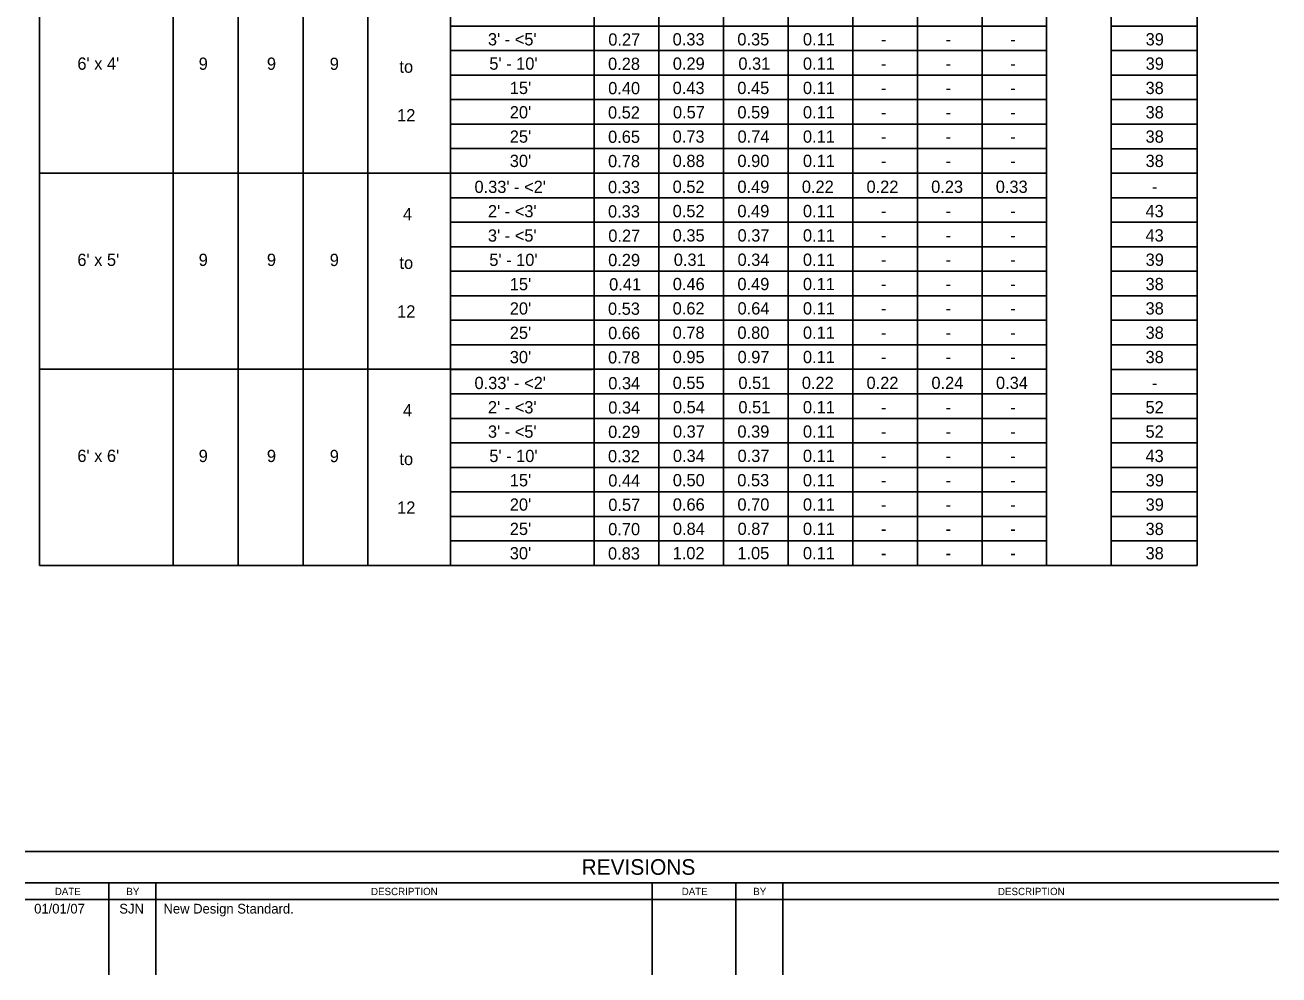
# Model space of a CAD drawing. Extents: x 10338.56 to 10340.78, y 76371.55 to 76372.62.
# Drawn here: x 10338.562 to 10339.206, y 76371.549 to 76372.037 of the extents above; entities that cross this region are included whole.
import ezdxf

# ---------------------------------------------------------------- set-up
doc = ezdxf.new("R2010")
doc.units = 0
for name, color, linetype in [('AdhocPoint_dp', 7, 'Continuous'), ('Border', 7, 'Continuous'), ('PlotBorder_dp', 7, 'Continuous')]:
    doc.layers.add(name, color=color, linetype=linetype)

msp = doc.modelspace()

# ---------------------------------------------------------------- linework, layer by layer
at = {"layer": 'Border'}
for p, q in [((10339.20638, 76371.61194), (10338.56226, 76371.61194)), ((10339.20638, 76371.59585), (10338.56226, 76371.59585)), ((10338.60528, 76371.59585), (10338.60528, 76371.54851)), ((10338.62945, 76371.59585), (10338.62945, 76371.54851)), ((10338.88433, 76371.59585), (10338.88433, 76371.54851)), ((10338.92735, 76371.59585), (10338.92735, 76371.54851)), ((10338.95152, 76371.59585), (10338.95152, 76371.54851)), ((10338.56226, 76371.58731), (10339.20638, 76371.58731))]:
    msp.add_line(p, q, dxfattribs=at)
at = {"layer": 'PlotBorder_dp'}
for p, q in [((10338.5697, 76372.53475), (10338.5697, 76371.75893)), ((10339.16444, 76372.53475), (10339.16444, 76371.75893)), ((10338.63833, 76372.51488), (10338.63833, 76371.75893)), ((10338.78078, 76372.51488), (10338.78078, 76371.75893)), ((10338.85466, 76372.51488), (10338.85466, 76371.75893)), ((10339.12025, 76372.51488), (10339.12025, 76371.75893)), ((10338.67169, 76372.50228), (10338.67169, 76371.75893)), ((10338.70506, 76372.50228), (10338.70506, 76371.75893)), ((10338.73842, 76372.50228), (10338.73842, 76371.75893)), ((10338.88786, 76372.47713), (10338.88786, 76371.75893)), ((10338.92106, 76372.47713), (10338.92106, 76371.75893)), ((10338.95425, 76372.47713), (10338.95425, 76371.75893)), ((10338.98745, 76372.47713), (10338.98745, 76371.75893)), ((10339.02065, 76372.47713), (10339.02065, 76371.75893)), ((10339.02065, 76372.47713), (10339.02065, 76371.75893)), ((10339.05385, 76372.47713), (10339.05385, 76371.75893)), ((10339.08705, 76372.47713), (10339.08705, 76371.75893)), ((10338.78078, 76372.03613), (10339.08705, 76372.03613)), ((10339.12025, 76372.03611), (10339.16444, 76372.03611)), ((10338.78078, 76372.02353), (10339.08705, 76372.02353)), ((10339.12025, 76372.02351), (10339.16444, 76372.02351)), ((10338.78078, 76372.01093), (10339.08705, 76372.01093)), ((10339.12025, 76372.01091), (10339.16444, 76372.01091)), ((10338.78078, 76371.99833), (10339.08705, 76371.99833)), ((10339.12025, 76371.99831), (10339.16444, 76371.99831)), ((10338.78078, 76371.98573), (10339.08705, 76371.98573)), ((10339.12025, 76371.98571), (10339.16444, 76371.98571)), ((10338.78078, 76371.97313), (10339.08705, 76371.97313)), ((10339.12025, 76371.97311), (10339.16444, 76371.97311)), ((10338.5697, 76371.96053), (10339.08705, 76371.96053)), ((10338.78139, 76371.96051), (10338.85356, 76371.96051)), ((10338.78139, 76371.96051), (10338.85356, 76371.96051)), ((10339.12025, 76371.96051), (10339.16444, 76371.96051)), ((10338.78078, 76371.94793), (10339.08705, 76371.94793)), ((10339.12025, 76371.94791), (10339.16444, 76371.94791)), ((10338.78078, 76371.93533), (10339.08705, 76371.93533)), ((10339.12025, 76371.93531), (10339.16444, 76371.93531)), ((10338.78078, 76371.92273), (10339.08705, 76371.92273)), ((10339.12025, 76371.92271), (10339.16444, 76371.92271)), ((10338.78078, 76371.91013), (10339.08705, 76371.91013)), ((10339.12025, 76371.91011), (10339.16444, 76371.91011)), ((10338.78078, 76371.89753), (10339.08705, 76371.89753)), ((10339.12025, 76371.89751), (10339.16444, 76371.89751)), ((10338.78078, 76371.88493), (10339.08705, 76371.88493)), ((10339.12025, 76371.88491), (10339.16444, 76371.88491)), ((10338.78078, 76371.87233), (10339.08705, 76371.87233)), ((10339.12025, 76371.87231), (10339.16444, 76371.87231)), ((10338.5697, 76371.85973), (10339.08705, 76371.85973)), ((10338.78139, 76371.85971), (10338.85356, 76371.85971)), ((10338.78139, 76371.85971), (10338.85356, 76371.85971)), ((10338.78139, 76371.85971), (10338.85356, 76371.85971)), ((10339.12025, 76371.85971), (10339.16444, 76371.85971)), ((10338.78078, 76371.84713), (10339.08705, 76371.84713)), ((10339.12025, 76371.84711), (10339.16444, 76371.84711)), ((10338.78078, 76371.83453), (10339.08705, 76371.83453)), ((10339.12025, 76371.83451), (10339.16444, 76371.83451)), ((10338.78078, 76371.82193), (10339.08705, 76371.82193)), ((10339.12025, 76371.82191), (10339.16444, 76371.82191)), ((10338.78078, 76371.80933), (10339.08705, 76371.80933)), ((10339.12025, 76371.80931), (10339.16444, 76371.80931)), ((10338.78078, 76371.79673), (10339.08705, 76371.79673)), ((10339.12025, 76371.79671), (10339.16444, 76371.79671)), ((10338.78078, 76371.78413), (10339.08705, 76371.78413)), ((10339.12025, 76371.78411), (10339.16444, 76371.78411)), ((10338.78078, 76371.77153), (10339.08705, 76371.77153)), ((10339.12025, 76371.77151), (10339.16444, 76371.77151)), ((10338.5697, 76371.75893), (10339.16444, 76371.75893)), ((10338.78139, 76371.75891), (10338.85356, 76371.75891))]:
    msp.add_line(p, q, dxfattribs=at)

# ---------------------------------------------------------------- texts
at = {"layer": 'AdhocPoint_dp'}
for s, height, p in [('9', 0.0063, (10338.65145, 76372.01363)), ('9', 0.0063, (10338.68649, 76372.01363)), ('9', 0.0063, (10338.71878, 76372.01357)), ('9', 0.0063, (10338.65145, 76371.91285)), ('9', 0.0063, (10338.68649, 76371.91285)), ('9', 0.0063, (10338.71878, 76371.91279)), ('9', 0.0063, (10338.65145, 76371.81206)), ('9', 0.0063, (10338.68649, 76371.81206)), ('9', 0.0063, (10338.71878, 76371.81201)), ('REVISIONS', 0.008022, (10338.84816, 76371.59996)), ('BY', 0.003753, (10338.61427, 76371.58952)), ('BY', 0.003753, (10338.93633, 76371.58952)), ('01/01/07', 0.005, (10338.56694, 76371.58005)), ('SJN', 0.005, (10338.61067, 76371.58005)), ('New Design Standard.', 0.005, (10338.63337, 76371.58005))]:
    msp.add_text(s, height=height, dxfattribs=at).set_placement(p)
for s, height, rotation, p in [('DATE', 0.003737, 359.86925, (10338.57753, 76371.58955)), ('DESCRIPTION', 0.0037522, 0.04975, (10338.73996, 76371.58951)), ('DATE', 0.003737, 359.86925, (10338.89959, 76371.58955)), ('DESCRIPTION', 0.0037522, 0.04975, (10339.06203, 76371.58951))]:
    msp.add_text(s, height=height, rotation=rotation, dxfattribs=at).set_placement(p)
at = {"layer": 'PlotBorder_dp'}
for s, p in [("3' - <5'", (10338.80003, 76372.02618)), ('0.27', (10338.86188, 76372.02608)), ('0.33', (10338.89493, 76372.02618)), ('0.35', (10338.92816, 76372.02618)), ('0.11', (10338.96186, 76372.02618)), ('39', (10339.1379, 76372.02618)), ('-', (10339.00192, 76372.02618)), ('-', (10339.03513, 76372.02618)), ('-', (10339.06832, 76372.02618)), ("6' x 4'", (10338.58913, 76372.01368)), ('to', (10338.75458, 76372.01213)), ("5' - 10'", (10338.80075, 76372.01368)), ('0.28', (10338.86175, 76372.01358)), ('0.29', (10338.895, 76372.01368)), ('0.31', (10338.9287, 76372.01368)), ('0.11', (10338.96186, 76372.01368)), ('39', (10339.1379, 76372.01368)), ('-', (10339.00192, 76372.01368)), ('-', (10339.03513, 76372.01368)), ('-', (10339.06832, 76372.01368)), ("15'", (10338.81126, 76372.00118)), ('0.40', (10338.86181, 76372.00108)), ('0.43', (10338.89493, 76372.00118)), ('0.45', (10338.92816, 76372.00118)), ('0.11', (10338.96186, 76372.00118)), ('38', (10339.13786, 76372.00118)), ('-', (10339.00192, 76372.00118)), ('-', (10339.03513, 76372.00118)), ('-', (10339.06832, 76372.00118)), ('12', (10338.7534, 76371.98713)), ("20'", (10338.81126, 76371.98868)), ('0.52', (10338.86173, 76371.98858)), ('0.57', (10338.89507, 76371.98868)), ('0.59', (10338.9282, 76371.98868)), ('0.11', (10338.96186, 76371.98868)), ('38', (10339.13786, 76371.98868)), ('-', (10339.00192, 76371.98868)), ('-', (10339.03513, 76371.98868)), ('-', (10339.06832, 76371.98868)), ("25'", (10338.81126, 76371.97618)), ('0.65', (10338.86176, 76371.97608)), ('0.73', (10338.89493, 76371.97618)), ('0.74', (10338.92826, 76371.97618)), ('0.11', (10338.96186, 76371.97618)), ('-', (10339.00192, 76371.97618)), ('-', (10339.03513, 76371.97618)), ('-', (10339.06832, 76371.97618)), ('38', (10339.13786, 76371.97618)), ("30'", (10338.81126, 76371.96368)), ('0.78', (10338.86175, 76371.96358)), ('0.88', (10338.89495, 76371.96368)), ('0.90', (10338.92821, 76371.96368)), ('0.11', (10338.96186, 76371.96368)), ('-', (10339.00192, 76371.96368)), ('-', (10339.03513, 76371.96368)), ('-', (10339.06832, 76371.96368)), ('38', (10339.13786, 76371.96368)), ("0.33' - <2'", (10338.79313, 76371.95035)), ('0.33', (10338.86173, 76371.95024)), ('0.52', (10338.89493, 76371.9504)), ('0.49', (10338.9282, 76371.9504)), ('0.22', (10338.96129, 76371.9504)), ('0.22', (10338.99452, 76371.9504)), ('0.23', (10339.02773, 76371.9504)), ('0.33', (10339.06091, 76371.9504)), ('-', (10339.14117, 76371.9504)), ('4', (10338.75636, 76371.93633)), ("2' - <3'", (10338.80003, 76371.93785)), ('0.33', (10338.86173, 76371.93774)), ('0.52', (10338.89493, 76371.9379)), ('0.49', (10338.9282, 76371.9379)), ('0.11', (10338.96186, 76371.9379)), ('-', (10339.00192, 76371.9379)), ('-', (10339.03513, 76371.9379)), ('-', (10339.06832, 76371.9379)), ('43', (10339.13783, 76371.9379)), ("3' - <5'", (10338.80003, 76371.92535)), ('0.27', (10338.86188, 76371.92524)), ('0.35', (10338.89496, 76371.9254)), ('0.37', (10338.92827, 76371.9254)), ('0.11', (10338.96186, 76371.9254)), ('-', (10339.00192, 76371.9254)), ('-', (10339.03513, 76371.9254)), ('-', (10339.06832, 76371.9254)), ('43', (10339.13783, 76371.9254)), ("6' x 5'", (10338.58913, 76371.91285)), ('to', (10338.75458, 76371.91133)), ("5' - 10'", (10338.80075, 76371.91285)), ('0.29', (10338.8618, 76371.91274)), ('0.31', (10338.8955, 76371.9129)), ('0.34', (10338.92826, 76371.9129)), ('0.11', (10338.96186, 76371.9129)), ('-', (10339.00192, 76371.9129)), ('-', (10339.03513, 76371.9129)), ('-', (10339.06832, 76371.9129)), ('39', (10339.1379, 76371.9129)), ("15'", (10338.81126, 76371.90035)), ('0.41', (10338.8623, 76371.90024)), ('0.46', (10338.895, 76371.9004)), ('0.49', (10338.9282, 76371.9004)), ('0.11', (10338.96186, 76371.9004)), ('-', (10339.00192, 76371.9004)), ('-', (10339.03513, 76371.9004)), ('-', (10339.06832, 76371.9004)), ('38', (10339.13786, 76371.9004)), ('12', (10338.7534, 76371.88633)), ("20'", (10338.81126, 76371.88785)), ('0.53', (10338.86173, 76371.88774)), ('0.62', (10338.89493, 76371.8879)), ('0.64', (10338.92826, 76371.8879)), ('0.11', (10338.96186, 76371.8879)), ('-', (10339.00192, 76371.8879)), ('-', (10339.03513, 76371.8879)), ('-', (10339.06832, 76371.8879)), ('38', (10339.13786, 76371.8879)), ("25'", (10338.81126, 76371.87535)), ('0.66', (10338.8618, 76371.87524)), ('0.78', (10338.89495, 76371.8754)), ('0.80', (10338.92821, 76371.8754)), ('0.11', (10338.96186, 76371.8754)), ('-', (10339.00192, 76371.8754)), ('-', (10339.03513, 76371.8754)), ('-', (10339.06832, 76371.8754)), ('38', (10339.13786, 76371.8754)), ('0.95', (10338.89496, 76371.8629)), ('0.97', (10338.92827, 76371.8629)), ('0.11', (10338.96186, 76371.8629)), ('38', (10339.13786, 76371.8629)), ("30'", (10338.81126, 76371.86285)), ('0.78', (10338.86175, 76371.86274)), ('-', (10339.00192, 76371.8629)), ('-', (10339.03513, 76371.8629)), ('-', (10339.06832, 76371.8629)), ("0.33' - <2'", (10338.79313, 76371.84957)), ('0.34', (10338.86186, 76371.84946)), ('0.55', (10338.89496, 76371.84962)), ('0.51', (10338.9287, 76371.84962)), ('0.22', (10338.96129, 76371.84962)), ('0.22', (10338.99452, 76371.84962)), ('0.24', (10339.02786, 76371.84962)), ('0.34', (10339.06104, 76371.84962)), ('-', (10339.14117, 76371.84957)), ('4', (10338.75636, 76371.83553)), ("2' - <3'", (10338.80003, 76371.83707)), ('0.34', (10338.86186, 76371.83696)), ('0.54', (10338.89506, 76371.83712)), ('0.51', (10338.9287, 76371.83712)), ('0.11', (10338.96186, 76371.83712)), ('-', (10339.00192, 76371.83712)), ('-', (10339.03513, 76371.83712)), ('-', (10339.06832, 76371.83712)), ('52', (10339.13784, 76371.83707)), ("3' - <5'", (10338.80003, 76371.82457)), ('0.29', (10338.8618, 76371.82446)), ('0.37', (10338.89507, 76371.82462)), ('0.39', (10338.9282, 76371.82462)), ('0.11', (10338.96186, 76371.82462)), ('52', (10339.13784, 76371.82457)), ('-', (10339.00192, 76371.82462)), ('-', (10339.03513, 76371.82462)), ('-', (10339.06832, 76371.82462)), ("6' x 6'", (10338.58913, 76371.81212)), ("5' - 10'", (10338.80075, 76371.81207)), ('0.32', (10338.86173, 76371.81196)), ('0.34', (10338.89506, 76371.81212)), ('0.37', (10338.92827, 76371.81212)), ('0.11', (10338.96186, 76371.81212)), ('43', (10339.13783, 76371.81207)), ('to', (10338.75458, 76371.81053)), ('-', (10339.00192, 76371.81212)), ('-', (10339.03513, 76371.81212)), ('-', (10339.06832, 76371.81212)), ("15'", (10338.81126, 76371.79957)), ('0.44', (10338.86186, 76371.79946)), ('0.50', (10338.89501, 76371.79962)), ('0.53', (10338.92813, 76371.79962)), ('0.11', (10338.96186, 76371.79962)), ('39', (10339.1379, 76371.79957)), ('-', (10339.00192, 76371.79962)), ('-', (10339.03513, 76371.79962)), ('-', (10339.06832, 76371.79962)), ("20'", (10338.81126, 76371.78707)), ('0.57', (10338.86188, 76371.78696)), ('0.66', (10338.895, 76371.78712)), ('0.70', (10338.92821, 76371.78712)), ('0.11', (10338.96186, 76371.78712)), ('39', (10339.1379, 76371.78707)), ('12', (10338.7534, 76371.78553)), ('-', (10339.00192, 76371.78712)), ('-', (10339.03513, 76371.78712)), ('-', (10339.06832, 76371.78712)), ("25'", (10338.81126, 76371.77457)), ('0.70', (10338.86181, 76371.77446)), ('0.84', (10338.89506, 76371.77462)), ('0.87', (10338.92827, 76371.77462)), ('0.11', (10338.96186, 76371.77462)), ('38', (10339.13786, 76371.77457)), ('-', (10339.00192, 76371.77462)), ('-', (10339.03513, 76371.77462)), ('-', (10339.06832, 76371.77462)), ("30'", (10338.81126, 76371.76207)), ('0.83', (10338.86173, 76371.76196)), ('1.02', (10338.89493, 76371.76212)), ('1.05', (10338.92816, 76371.76212)), ('0.11', (10338.96186, 76371.76212)), ('38', (10339.13786, 76371.76207)), ('-', (10339.00192, 76371.76212)), ('-', (10339.03513, 76371.76212)), ('-', (10339.06832, 76371.76212))]:
    msp.add_text(s, height=0.0063, dxfattribs=at).set_placement(p)

doc.saveas('drawing.dxf')
